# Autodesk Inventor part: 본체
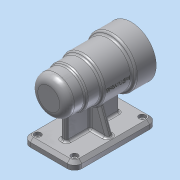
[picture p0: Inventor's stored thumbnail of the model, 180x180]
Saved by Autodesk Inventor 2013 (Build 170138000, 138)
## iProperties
Created: 2016-06
Part Number: 본체
Material: 알루미늄 6061
Document SubType Name: Modeling
Designer: dgall
Density: 2.71 g/cm^3
Mass: 671.782 g
Surface Area: 647.018 cm^2
Volume: 247.89 cm^3
Author: dgall
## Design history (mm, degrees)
sketch "스케치1"
  geometry: L1 (-56, 0)-(56, 0); L2 (-56, 0)-(-56, 25); L3 (-56, 25)-(-31, 25); L4 (-31, 25)-(-31, 27); L5 (-31, 27)-(-11, 27); L6 (-11, 27)-(-11, 30); L7 (-11, 30)-(28, 30); L8 (28, 30)-(28, 34); L9 (28, 34)-(56, 34); L10 (56, 34)-(56, 0); 2 further points
  constraints: 20 end point, 6 parallel, 2 perpendicular, 1 coincident, 1 horizontal, 1 midpoint, 1 vertical
  dimensions: "d0" = 112 distance of L1.start L1.end; "d2" = 25 distance between parallel lines of L4 L2; "d3" = 45 distance between parallel lines of L6 L2; "d4" = 84 distance between parallel lines of L8 L2; "d5" = 50 diameter of L3 L1; "d6" = 54 diameter of L5 L1; "d7" = 60 diameter of L7 L1; "d8" = 68 diameter of L9 L1
revolve "회전1" sketch "스케치1" stored, may be unused: angle "d9" = 90 deg
sketch "스케치2"
  geometry: L1 (-50, 0)-(56, 0); L2 (56, -34)-(56, 34) reference; L3 (56, 21)-(41, 21); L4 (41, 21)-(41, 24); L5 (41, 24)-(-13, 24); L6 (-13, 24)-(-13, 21); L7 (-13, 21)-(-25, 21); L8 (-25, 21)-(-25, 17.5); L9 (-25, 17.5)-(-43, 17.5); L10 (-43, 17.5)-(-43, 16); L11 (-43, 16)-(-47, 16); L12 (-47, 16)-(-47, 10.5); L13 (-47, 10.5)-(-50, 10.5); L14 (-50, 10.5)-(-50, 0); 1 further point
  constraints: 26 end point, 9 parallel, 2 perpendicular, 2 point on line, 1 collinear, 1 horizontal, 1 midpoint
  dimensions: "d10" = 21 diameter of L13 L1; "d12" = 32 diameter of L11 L1; "d13" = 35 diameter of L9 L1; "d14" = 42 diameter of L7 L1; "d15" = 48 diameter of L5 L1; "d16" = 42 diameter of L3 L1; "d17" = 3 distance between parallel lines of L12 L14; "d19" = 18 distance between parallel lines of L8 L10; "d20" = 12 distance between parallel lines of L6 L8; "d21" = 54 distance between parallel lines of L4 L6; "d22" = 15 distance between parallel lines of L2 L4; "d92" = 4 distance between parallel lines of L10 L12
revolve "회전2" sketch "스케치2" stored, may be unused: angle "d23" = 90 deg
node "작업 평면1"
sketch "스케치3"
  geometry: L1 (34, 56)-(-34, 56) reference; L2 (-35, 56)-(-35, -56); L3 (-35, -56)-(35, -56); L4 (35, -56)-(35, 56); L5 (-35, 56)-(35, 56); 2 further points
  constraints: 8 end point, 3 perpendicular, 2 point on line, 1 collinear, 1 midpoint, 1 vertical alignment
  dimensions: "d25" = 70 distance of L2.start L4.end; "d27" = 112 distance of L2.start L2.end
extrude "돌출1" join sketch "스케치3" distance "d28" = 10; taper "d29" = 0 deg
sketch "스케치4"
  geometry: L1 (-4, -36)-(-4, 36); L2 (4, 36)-(4, -36); L3 (-4, 36)-(4, 36); L4 (-4, -36)-(4, -36); L5 (-35, 56)-(35, 56) reference; 4 further points
  constraints: 8 end point, 3 midpoint, 2 parallel, 2 vertical alignment, 1 horizontal alignment, 1 perpendicular, 1 vertical
  dimensions: "d30" = 8 distance between parallel lines of L2 L1; "d32" = 20 distance between parallel lines of L5 L3
extrude "돌출2" join sketch "스케치4" stored distance "d33" = 10; taper "d34" = 0 deg
node "작업 평면2"
sketch "스케치5"
  geometry: L1 (70, 0)-(0, 0) reference; L2 (7, 0)-(16.995, 27.462); L3 (0, 0)-(0, -10) reference; 1 further point
  constraints: 2 end point, 1 point on line
  dimensions: "d35" = 7 distance from line of L3 L2.start; "d36" = 110 deg angle of L1 L2
feature "리브1" sketch "스케치5" dims "d37" = 1, "d38" = 8, "d39" = 0, "d40" = 0, "d41" = 1, "d42" = 1
sketch "스케치6"
  geometry: L1 (0, 0)-(0, 26); C1 r 34 at (0, 0) reference; 1 further point
  constraints: 2 end point, 1 coincident, 1 vertical
  dimensions: "d43" = 26 distance of L1.start L1.end
hole "구멍1" sketch "스케치6" at (0, 26) diameter "d44" = 3.242; stored, may be unused: countersink angle "d48" = 90 deg, drill point angle "d50" = 118 deg; dims "d45" = 8, "d46" = 4, "d47" = 2, "d49" = 11
node "작업 평면3"
sketch "스케치7"
  geometry: L1 (47.5, -34)-(47.5, 34) reference; 2 further points
  constraints: 1 horizontal alignment, 1 other
  dimensions: "d54" = 48 distance from line of L1 point (-0.5, 0)
feature "엠보싱1" sketch "스케치7" dims "d0" = 112, "d2" = 25, "d3" = 45, "d4" = 84, "d5" = 50, "d6" = 54, "d7" = 60, "d8" = 68, "d10" = 21, "d12" = 32, "d13" = 35, "d14" = 42, "d15" = 48, "d16" = 42, "d17" = 3, "d19" = 18, "d20" = 12, "d21" = 54, "d22" = 15, "d55" = 0.5, "d56" = 0, "d92" = 4
fillet "모깎기5" dims "d87" = 3, "d88" = 0.3
chamfer "모따기2" distance "d89" = 1; stored, may be unused: second distance "d90" = 2, angle "d91" = 45 deg
fillet "모깎기6" dims "d93" = 10
fillet "모깎기7" dims "d94" = 3
fillet "모깎기8" dims "d95" = 3
fillet "모깎기9" dims "d96" = 3
chamfer "모따기3" distance "d97" = 4; stored, may be unused: second distance "d98" = 2, angle "d99" = 45 deg
hole "구멍4" diameter "d102" = 5; stored, may be unused: countersink angle "d106" = 90 deg, drill point angle "d108" = 118 deg; dims "d100" = 10, "d101" = 10, "d103" = 6, "d104" = 9, "d105" = 4, "d107" = 8
hole "구멍5" diameter "d111" = 5; stored, may be unused: countersink angle "d115" = 90 deg, drill point angle "d117" = 118 deg; dims "d109" = 10, "d110" = 10, "d112" = 6, "d113" = 9, "d114" = 4, "d116" = 8
node "솔리드1"
mirror "대칭1"
pattern_circular "원형 패턴1" dims angle "d52" = 360 deg
mirror "대칭3"
